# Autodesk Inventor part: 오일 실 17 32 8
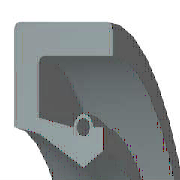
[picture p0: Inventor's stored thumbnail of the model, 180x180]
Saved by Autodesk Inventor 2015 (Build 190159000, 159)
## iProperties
IsCustomPart: 1
Created: 2012-02
Part Number: 오일 실 17 32 8
Material: 고무
Description: 오일-실
Document SubType Name: Modeling
Standard: KS B 2804
Designer: test
Standards Organization: KS
Language: ko-KR
Size Designation: S - 17 32 8
Categories: <MemberInstance><Categories><Category DisplayName="샤프트 부품" InternalName="7f7aeb1f-a693-4053-b835-cee3144e0d98" Mnemonic="SHFT"><Category DisplayName="실링" Intern
Density: 0.93 g/cm^3
Appearance: 고무 - 검은색 - 버전 1.1
Author: test
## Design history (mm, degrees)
revolve "본체" stored, may be unused: angle "d17" = 90 deg
revolve "스프링1" stored, may be unused: angle "d18" = 90 deg
body "Solid1"
sketch "스케치1"
  geometry: L1 (0, 16)-(8, 16); L2 (8, 16)-(8, 14.75); L3 (8, 14.75)-(1.75, 14.75); L4 (0, 16)-(0, 10.6); L5 (0, 10.6)-(1.75, 10.25); L6 (1.75, 10.25)-(4.9, 8.5); L7 (4.9, 8.5)-(0, 8.5); L8 (6.3, 9.375)-(6.3, 10.6); L9 (0, 0)-(9.586, 0) reference; L10 (4.9, 8.5)-(6.3, 9.375); L11 (0, 18)-(0, -3) reference; L12 (-1.917, 0)-(11.503, 0) reference; L13 (4.2, 10.6)-(1.75, 11.09); L14 (1.75, 11.09)-(1.75, 14.75); L15 (6.3, 10.6)-(5.6, 10.6); C1 r 0.455 at (4.9, 10.6); A1 r 0.7 centre (4.9, 10.6) between (5.6, 10.6) and (4.2, 10.6)
  constraints: 26 end point, 5 horizontal alignment, 4 perpendicular, 2 centre point, 2 collinear, 2 horizontal, 2 parallel, 2 point on circle, 2 point on line, 2 vertical alignment, 1 coincident
  dimensions: "d0" = 32 diameter of L1 L9 (= SD2); "d1" = 18.75 diameter of L8.start L9 (= ABDM); "d2" = 1.25 distance of L1.end L2.end (computed from SD); "d3" = 0.91 diameter of C1 (= SPDI); "d4" = 1.4 diameter of A1 (= SPDA); "d5" = 17 diameter of L6.end L9 (= NND); "d6" = 20.5 diameter of L5.end L9 (= TKDM); "d7" = 21.2 diameter of L4.end L9 (= HLDM); "d8" = 4.9 distance from line of C1.centre L4 (= SPDST); "d9" = 6.3 distance between parallel lines of L8 L4 (= SDI); "d10" = 8 distance between parallel lines of L2 L4 (= SWDT); "d12" = 1.75 distance between parallel lines of L14 L4 (= SD)
fillet "모깎기1" dims "d11" = 0.3 (= RR)
other parameters: "SD2" = 32 [user parameter; used in 1 equation term], "SWDT" = 8 [user parameter; used in 1 equation term], "RR" = 0.3 [user parameter; used in 1 equation term], "SD" = 1.75 [user parameter; used in 2 equation terms], "NND" = 17 [user parameter; used in 1 equation term], "SPDA" = 1.4 [user parameter; used in 1 equation term], "SPDI" = 0.91 [user parameter; used in 1 equation term], "TKDM" = 20.5 [user parameter; used in 1 equation term], "HLDM" = 21.2 [user parameter; used in 1 equation term], "ABDM" = 18.75 [user parameter; used in 1 equation term], "SDI" = 6.3 [user parameter; used in 1 equation term], "SPDST" = 4.9 [user parameter; used in 1 equation term], "d13" = 0, "d14" = 0, "d15" = 0, "LAB" = 0.35 [user parameter]
